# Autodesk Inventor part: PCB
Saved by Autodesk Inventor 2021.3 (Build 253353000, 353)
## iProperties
Created: 2023-02
Part Number: PCB
Material: Generic
Document SubType Name: Modeling
Designer: AdminForWorker
Density: 1 g/cm^3
Appearance: Default
Title: PCB
Author: AdminForWorker
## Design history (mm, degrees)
feature "Body1"
feature "Body3"
feature "Body4"
feature "Body5"
feature "Body6"
feature "Body7"
feature "Body8"
feature "Body9"
feature "Body10"
feature "Body11"
feature "Body12"
feature "Body13"
feature "Body14"
feature "Body15"
body "Solid1"
body "Solid2"
body "Solid3"
body "Solid4"
body "Solid5"
body "Solid6"
body "Solid7"
body "Solid8"
body "Solid9"
body "Solid10"
body "Solid11"
body "Solid12"
body "Solid13"
body "Solid14"
